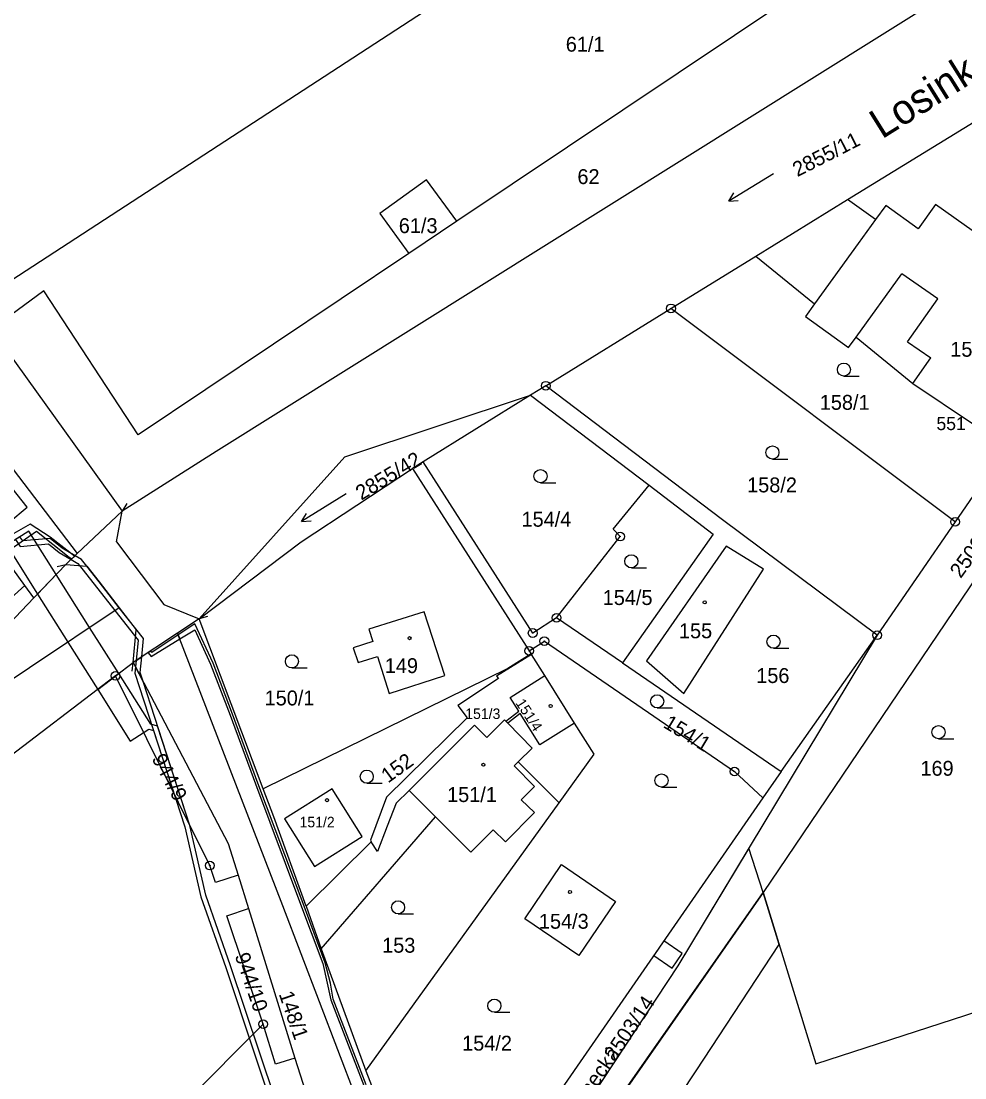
# Model space of a CAD drawing. Extents: x -562167 to -556918, y -1077891 to -1070763.
# Drawn here: x -558406.7 to -558298.9, y -1073028.6 to -1072907.9 of the extents above; entities that cross this region are included whole.
import ezdxf

# ---------------------------------------------------------------- set-up
doc = ezdxf.new("R2010")
doc.units = 0
for name, color, linetype in [('Hranice parcel', 7, 'Continuous'), ('Parcelní čísla', 7, 'Continuous'), ('Pop  PČ popisy', 7, 'Continuous'), ('Vnitřní kresba', 7, 'Continuous'), ('Věcná břemena k části', 7, 'Continuous'), ('Značky bodu BP', 7, 'Continuous'), ('Značky budov', 7, 'Continuous'), ('Značky kultur', 7, 'Continuous')]:
    doc.layers.add(name, color=color, linetype=linetype)

msp = doc.modelspace()

# ---------------------------------------------------------------- linework, layer by layer
at = {"layer": 'Hranice parcel'}
for p, q in [((-558412.27, -1072940.34), (-558302.75, -1072869.11)), ((-558360.38, -1072926.01), (-558365.72, -1072929.88)), ((-558356.9, -1072930.74), (-558360.38, -1072926.01)), ((-558322.75, -1072934.72), (-558312.27, -1072928.27)), ((-558309.07, -1072930.54), (-558312.27, -1072928.27)), ((-558365.72, -1072929.88), (-558362.39, -1072934.42)), ((-558307.91, -1072928.94), (-558309.07, -1072930.54)), ((-558356.9, -1072930.74), (-558362.39, -1072934.42)), ((-558332.45, -1072940.7), (-558322.75, -1072934.72)), ((-558322.75, -1072934.72), (-558316.04, -1072940.16)), ((-558346.76, -1072949.53), (-558332.45, -1072940.7)), ((-558299.99, -1072965.07), (-558332.45, -1072940.7)), ((-558410.09, -1072943.08), (-558395.16, -1072963.84)), ((-558346.76, -1072949.53), (-558348.49, -1072950.6)), ((-558348.49, -1072950.6), (-558360.75, -1072958.22)), ((-558348.49, -1072950.6), (-558334.96, -1072960.89)), ((-558360.75, -1072958.22), (-558361.97, -1072958.98)), ((-558348.25, -1072977.77), (-558360.75, -1072958.22)), ((-558361.97, -1072958.98), (-558348.65, -1072979.81)), ((-558339.04, -1072965.93), (-558334.96, -1072960.89)), ((-558400.29, -1072968.7), (-558395.16, -1072963.84)), ((-558299.99, -1072965.07), (-558308.9, -1072978.03)), ((-558400.29, -1072968.7), (-558401.61, -1072969.95)), ((-558401.61, -1072969.95), (-558405.23, -1072973.76)), ((-558462.61, -1073022.54), (-558406.26, -1072972.36)), ((-558405.23, -1072973.76), (-558406.26, -1072972.36)), ((-558386.36, -1072976.14), (-558388.83, -1072977.78)), ((-558379.04, -1072995.57), (-558386.36, -1072976.14)), ((-558345.52, -1072976.03), (-558348.25, -1072977.77)), ((-558338, -1072981.18), (-558345.52, -1072976.03)), ((-558388.83, -1072977.78), (-558393.89, -1072981.14)), ((-558319.87, -1072993.6), (-558308.9, -1072978.03)), ((-558348.65, -1072979.81), (-558346.92, -1072978.7)), ((-558346.92, -1072978.7), (-558325.2, -1072993.59)), ((-558348.65, -1072979.81), (-558348.44, -1072980.14)), ((-558348.39, -1072980.22), (-558348.44, -1072980.14)), ((-558346.87, -1072982.64), (-558348.39, -1072980.22)), ((-558395.91, -1072982.67), (-558393.89, -1072981.14)), ((-558338, -1072981.18), (-558319.87, -1072993.6)), ((-558395.91, -1072982.67), (-558409.32, -1072992.86)), ((-558385.14, -1073004.33), (-558395.91, -1072982.67)), ((-558343.46, -1072988.05), (-558346.87, -1072982.64)), ((-558349.9, -1072992.48), (-558345.24, -1072997.18)), ((-558325.2, -1072993.59), (-558321.94, -1072996.58)), ((-558319.87, -1072993.6), (-558321.94, -1072996.58)), ((-558367.31, -1073027.78), (-558345.24, -1072997.18)), ((-558321.94, -1072996.58), (-558350.74, -1073038.18)), ((-558372.4, -1073013.83), (-558359.35, -1072998.75)), ((-558366.69, -1073001.61), (-558374.15, -1073008.96)), ((-558384.49, -1073006.28), (-558385.14, -1073004.33)), ((-558381.92, -1073005.41), (-558384.49, -1073006.28)), ((-558381.92, -1073005.41), (-558380.73, -1073009.23)), ((-558383.21, -1073010.07), (-558380.73, -1073009.23)), ((-558380.73, -1073009.23), (-558375.41, -1073026.31)), ((-558374.15, -1073008.96), (-558372.4, -1073013.83)), ((-558379.05, -1073022.44), (-558383.21, -1073010.07)), ((-558372.4, -1073013.83), (-558367.31, -1073027.78)), ((-558397.33, -1073040.74), (-558379.05, -1073022.44)), ((-558377.65, -1073026.99), (-558379.05, -1073022.44)), ((-558375.41, -1073026.31), (-558377.65, -1073026.99)), ((-558375.41, -1073026.31), (-558374.22, -1073030.13))]:
    msp.add_line(p, q, dxfattribs=at)
for points in [[(-558502.85, -1072847.47), (-558483.15, -1072864.47), (-558456.76, -1072894.62), (-558400.29, -1072968.7)], [(-558294.24, -1072880.85), (-558298.44, -1072890.96), (-558299.92, -1072892.58), (-558356.9, -1072930.74)], [(-558289.19, -1072887.81), (-558290.8, -1072891.97), (-558300.9, -1072904.77), (-558384.43, -1072957.06), (-558395.16, -1072963.84)], [(-558312.27, -1072928.27), (-558297.82, -1072919.38), (-558297.58, -1072919.21)], [(-558286.49, -1072939.41), (-558295.68, -1072933.46), (-558302.22, -1072928.82), (-558304.22, -1072931.62), (-558307.91, -1072928.94)], [(-558362.39, -1072934.42), (-558393.32, -1072955.13), (-558404.11, -1072938.68), (-558410.09, -1072943.08)], [(-558316.04, -1072940.16), (-558317.1, -1072941.63), (-558312.15, -1072945.18), (-558311.29, -1072944)], [(-558311.29, -1072944), (-558304.8, -1072949.26), (-558298.02, -1072953.85), (-558292.55, -1072945.86), (-558293.35, -1072945.29), (-558292.99, -1072944.69), (-558291.91, -1072944.56), (-558290.96, -1072943.22), (-558291.26, -1072942.13), (-558290.89, -1072941.55), (-558287.69, -1072942.86)], [(-558287.69, -1072942.86), (-558288.1, -1072946.44), (-558295.88, -1072959.09), (-558299.99, -1072965.07)], [(-558308.9, -1072978.03), (-558326.55, -1072964.86), (-558346.76, -1072949.53)], [(-558386.36, -1072976.14), (-558369.71, -1072957.67), (-558348.49, -1072950.6)], [(-558406.26, -1072972.36), (-558410.25, -1072966.91), (-558406.02, -1072963.38), (-558412.6, -1072955.11)], [(-558386.36, -1072976.14), (-558374.72, -1072967.37), (-558361.97, -1072958.98)], [(-558334.96, -1072960.89), (-558327.62, -1072966.48), (-558338, -1072981.18)], [(-558289.9, -1072961.05), (-558292.03, -1072963.19), (-558321.91, -1073007.39)], [(-558345.52, -1072976.03), (-558338.27, -1072966.76), (-558339.04, -1072965.93)], [(-558326.16, -1072967.85), (-558335.25, -1072980.94), (-558331, -1072984.68), (-558321.87, -1072970.49), (-558326.16, -1072967.85)], [(-558401.61, -1072969.95), (-558399.19, -1072970.13), (-558397.79, -1072971.93), (-558395.5, -1072974.88)], [(-558405.23, -1072973.76), (-558412.32, -1072981.19), (-558462.01, -1073023.32)], [(-558395.5, -1072974.88), (-558416.04, -1072988.58), (-558459.2, -1073023.8), (-558471.43, -1073037.29), (-558467.94, -1073057.14)], [(-558358.29, -1072982.64), (-558360.65, -1072975.35), (-558366.97, -1072977.34), (-558366.52, -1072978.75), (-558368.77, -1072979.46), (-558368.18, -1072981.15), (-558365.98, -1072980.45), (-558364.65, -1072984.66), (-558358.29, -1072982.64)], [(-558360.05, -1073052.77), (-558376.81, -1073008.93), (-558388.83, -1072977.78)], [(-558308.9, -1072978.03), (-558331.65, -1073015.79), (-558358.56, -1073056.51), (-558360.05, -1073052.77)], [(-558348.44, -1072980.14), (-558351.11, -1072981.83), (-558379.04, -1072995.57)], [(-558348.39, -1072980.22), (-558352.37, -1072982.69), (-558352.17, -1072982.97), (-558356.82, -1072986.06), (-558355.74, -1072987.46), (-558364.94, -1072996.53), (-558366.8, -1073001.43), (-558366.69, -1073001.61)], [(-558393.89, -1072981.14), (-558383.05, -1073001.79), (-558381.92, -1073005.41)], [(-558351.33, -1072987.85), (-558349.83, -1072986.71), (-558350.82, -1072985.12), (-558346.87, -1072982.64)], [(-558351.33, -1072987.85), (-558351.48, -1072987.69), (-558353.49, -1072989.7), (-558354.91, -1072988.29), (-558362.36, -1072995.74), (-558363.86, -1072997.19), (-558364.86, -1072999.81), (-558365.97, -1073002.72), (-558366.69, -1073001.61)], [(-558343.46, -1072988.05), (-558347.43, -1072990.54), (-558349.67, -1072986.97), (-558351.11, -1072988.06), (-558351.33, -1072987.85)], [(-558345.24, -1072997.18), (-558341.23, -1072991.61), (-558343.46, -1072988.05)], [(-558359.35, -1072998.75), (-558355.3, -1073002.8), (-558352.75, -1073000.26), (-558351.35, -1073001.6), (-558348.05, -1072998.26), (-558349.57, -1072996.82), (-558348.03, -1072995.3), (-558350.35, -1072992.93), (-558349.9, -1072992.48)], [(-558374.15, -1073008.96), (-558377.82, -1072998.76), (-558379.04, -1072995.57)], [(-558373.18, -1073004.43), (-558367.72, -1073001), (-558371.16, -1072995.55), (-558376.62, -1072998.98), (-558373.18, -1073004.43)], [(-558342.98, -1073014.61), (-558349.16, -1073010.4), (-558344.95, -1073004.22), (-558338.78, -1073008.45), (-558342.98, -1073014.61)], [(-558321.91, -1073007.39), (-558348.49, -1073045.41), (-558357.24, -1073057.99)], [(-558321.91, -1073007.39), (-558315.9, -1073026.96), (-558290.19, -1073018.62)], [(-558367.31, -1073027.78), (-558362.99, -1073039.01), (-558356.93, -1073040.23), (-558352.91, -1073040.63), (-558350.74, -1073038.18)]]:
    msp.add_lwpolyline(points, dxfattribs=at)
at = {"layer": 'Vnitřní kresba'}
for p, q in [((-558309.07, -1072930.54), (-558311.07, -1072933.3)), ((-558311.07, -1072933.3), (-558316.04, -1072940.16)), ((-558311.29, -1072944), (-558306.06, -1072936.77)), ((-558301.97, -1072939.61), (-558306.06, -1072936.77)), ((-558305.42, -1072944.53), (-558301.97, -1072939.61)), ((-558305.42, -1072944.53), (-558302.77, -1072946.35)), ((-558304.8, -1072949.26), (-558302.77, -1072946.35)), ((-558394.64, -1072962.98), (-558395.16, -1072963.84)), ((-558395.82, -1072967.36), (-558395.16, -1072963.84)), ((-558395.82, -1072967.36), (-558394.29, -1072969.38)), ((-558394.29, -1072969.38), (-558390.4, -1072974.53)), ((-558402.58, -1072970.19), (-558401.61, -1072969.95)), ((-558390.4, -1072974.53), (-558386.36, -1072976.14)), ((-558395.5, -1072974.88), (-558393.54, -1072977.41)), ((-558385.39, -1072975.88), (-558386.36, -1072976.14)), ((-558393.89, -1072981.14), (-558393.54, -1072977.41)), ((-558394.03, -1072982.13), (-558393.89, -1072981.14)), ((-558351.11, -1072988.06), (-558348.3, -1072990.92)), ((-558349.9, -1072992.48), (-558348.3, -1072990.92)), ((-558362.36, -1072995.74), (-558361.55, -1072996.55)), ((-558361.55, -1072996.55), (-558359.35, -1072998.75))]:
    msp.add_line(p, q, dxfattribs=at)
at = {"layer": 'Věcná břemena k části'}
for points in [[(-558404.96, -1072966.15), (-558401.2, -1072969.12), (-558400.92, -1072969.3), (-558400.62, -1072969.01), (-558403.38, -1072966.82), (-558405.66, -1072965.34), (-558409.71, -1072967.64), (-558408.83, -1072968.85)], [(-558408.35, -1072967.75), (-558404.82, -1072973.33), (-558402.69, -1072971.09), (-558405.81, -1072966.15)], [(-558407.33, -1072967.11), (-558406.82, -1072967.9), (-558403.57, -1072967.6), (-558402.34, -1072968.59), (-558401, -1072969.37), (-558400.54, -1072968.94), (-558402, -1072968.09), (-558403.39, -1072966.98), (-558406.52, -1072967.26), (-558406.83, -1072966.79)], [(-558395.98, -1072975.2), (-558393.32, -1072978.58), (-558393.55, -1072980.92), (-558392.91, -1072980.49), (-558392.7, -1072978.4), (-558395.5, -1072974.88), (-558397.79, -1072971.93), (-558399.19, -1072970.13), (-558399.81, -1072969.37), (-558400.54, -1072968.94), (-558401, -1072969.37), (-558400.21, -1072969.83), (-558400.02, -1072970.07)], [(-558401.37, -1072978.8), (-558397.95, -1072984.22), (-558395.55, -1072982.4), (-558398.87, -1072977.13), (-558402.69, -1072971.09), (-558404.82, -1072973.33)], [(-558391.75, -1072980), (-558391.89, -1072979.81), (-558392.2, -1072980.02), (-558391.86, -1072980.45), (-558388.58, -1072978.44), (-558388.75, -1072977.99)], [(-558393.55, -1072980.92), (-558393.63, -1072981.64), (-558392.75, -1072983.32), (-558393.09, -1072982.28), (-558392.91, -1072980.49)], [(-558367.49, -1073062.05), (-558367.33, -1073060.92), (-558371.08, -1073052.48), (-558376.05, -1073035.85), (-558382.76, -1073015.77), (-558385.59, -1073007.72), (-558387.41, -1072999.74), (-558392.75, -1072983.32), (-558393.63, -1072981.64), (-558393.69, -1072982.34), (-558387.99, -1072999.9), (-558386.17, -1073007.88), (-558383.32, -1073015.97), (-558376.71, -1073035.79), (-558377.06, -1073035.98), (-558376.78, -1073036.51), (-558376.52, -1073036.37), (-558371.64, -1073052.68)], [(-558392.09, -1072988.76), (-558391.56, -1072988.89), (-558387.99, -1072999.9), (-558386.17, -1073007.88), (-558383.32, -1073015.97), (-558376.71, -1073035.79), (-558376.52, -1073036.37), (-558371.64, -1073052.68), (-558367.49, -1073062.05), (-558367.33, -1073060.92), (-558371.08, -1073052.48), (-558376.05, -1073035.85), (-558382.76, -1073015.77), (-558385.59, -1073007.72), (-558387.41, -1072999.74), (-558391.1, -1072988.39), (-558391.89, -1072988.19), (-558395.55, -1072982.4), (-558397.95, -1072984.22), (-558394.23, -1072990.11)], [(-558321.91, -1073007.39), (-558323.54, -1073002.33), (-558331.65, -1073015.79), (-558358.56, -1073056.51), (-558359.57, -1073058.1), (-558362.56, -1073062.72), (-558371.61, -1073078.42), (-558369.34, -1073079.8), (-558362.54, -1073067.55), (-558360.35, -1073074.19), (-558354.71, -1073065.77), (-558357.24, -1073057.99), (-558348.49, -1073045.41)], [(-558321.91, -1073007.39), (-558357.24, -1073057.99), (-558347.91, -1073055.5), (-558340.56, -1073044.32), (-558329.58, -1073027.78), (-558320.08, -1073013.34)], [(-558332.31, -1073016.05), (-558331.16, -1073014.38), (-558333.25, -1073012.93), (-558334.41, -1073014.6)]]:
    msp.add_lwpolyline(points, close=True, dxfattribs=at)
msp.add_lwpolyline([(-558367.28, -1073029.35), (-558371.03, -1073019.59), (-558371.36, -1073017.74), (-558371.95, -1073015.42), (-558374.6, -1073008.34), (-558379.65, -1072994.91), (-558382.54, -1072987.05), (-558384.77, -1072981.22), (-558386.85, -1072976.71), (-558388.75, -1072977.99), (-558388.58, -1072978.44), (-558386.87, -1072977.39), (-558385.05, -1072981.33), (-558382.81, -1072987.15), (-558379.93, -1072995.01), (-558374.88, -1073008.44), (-558372.23, -1073015.51), (-558371.32, -1073019.67), (-558367.56, -1073029.45)], dxfattribs=at)
at = {"layer": 'Značky bodu BP'}
for centre, radius in [((-558332.45, -1072940.7), 0.5), ((-558332.45, -1072940.7), 0.0303), ((-558346.76, -1072949.53), 0.5), ((-558346.76, -1072949.53), 0.0303), ((-558299.99, -1072965.07), 0.5), ((-558299.99, -1072965.07), 0.0303), ((-558338.27, -1072966.76), 0.5), ((-558338.27, -1072966.76), 0.0303), ((-558345.52, -1072976.03), 0.5), ((-558345.52, -1072976.03), 0.0303), ((-558348.25, -1072977.77), 0.5), ((-558348.25, -1072977.77), 0.0303), ((-558346.92, -1072978.7), 0.5), ((-558308.9, -1072978.03), 0.5), ((-558308.9, -1072978.03), 0.0303), ((-558348.65, -1072979.81), 0.5), ((-558346.92, -1072978.7), 0.0303), ((-558348.65, -1072979.81), 0.0303), ((-558395.91, -1072982.67), 0.5), ((-558395.91, -1072982.67), 0.0303), ((-558325.2, -1072993.59), 0.5), ((-558325.2, -1072993.59), 0.0303), ((-558385.14, -1073004.33), 0.5), ((-558385.14, -1073004.33), 0.0303), ((-558379.05, -1073022.44), 0.5), ((-558379.05, -1073022.44), 0.0303)]:
    msp.add_circle(centre, radius, dxfattribs=at)
at = {"layer": 'Značky budov'}
for centre in [(-558328.6, -1072974.27), (-558362.32, -1072978.36), (-558346.2, -1072986.1), (-558353.89, -1072992.82), (-558371.76, -1072996.86), (-558343.99, -1073007.35)]:
    msp.add_circle(centre, 0.175, dxfattribs=at)
at = {"layer": 'Značky kultur'}
for p, q in [((-558320.72, -1072925.35), (-558325.86, -1072928.44)), ((-558325.86, -1072928.44), (-558325.28, -1072927.5)), ((-558325.86, -1072928.44), (-558324.77, -1072928.36)), ((-558312.69, -1072948.44), (-558310.94, -1072948.44)), ((-558320.86, -1072957.91), (-558319.11, -1072957.91)), ((-558347.36, -1072960.61), (-558345.61, -1072960.61)), ((-558369.57, -1072961.87), (-558374.66, -1072965.05)), ((-558374.66, -1072965.05), (-558374.1, -1072964.11)), ((-558374.66, -1072965.05), (-558373.57, -1072964.96)), ((-558336.98, -1072970.33), (-558335.23, -1072970.33)), ((-558320.74, -1072979.51), (-558318.99, -1072979.51)), ((-558375.76, -1072981.76), (-558374.01, -1072981.76)), ((-558334.03, -1072986.32), (-558332.28, -1072986.32)), ((-558301.88, -1072989.85), (-558300.13, -1072989.85)), ((-558367.21, -1072994.92), (-558365.46, -1072994.92)), ((-558333.54, -1072995.36), (-558331.79, -1072995.36)), ((-558363.63, -1073009.85), (-558361.88, -1073009.85)), ((-558352.63, -1073021.08), (-558350.88, -1073021.08))]:
    msp.add_line(p, q, dxfattribs=at)
for centre in [(-558312.69, -1072947.69), (-558320.86, -1072957.16), (-558347.36, -1072959.86), (-558336.98, -1072969.58), (-558320.74, -1072978.76), (-558375.76, -1072981.01), (-558334.03, -1072985.57), (-558301.88, -1072989.1), (-558367.21, -1072994.17), (-558333.54, -1072994.61), (-558363.63, -1073009.1), (-558352.63, -1073020.33)]:
    msp.add_circle(centre, 0.75, dxfattribs=at)

# ---------------------------------------------------------------- texts
at = {"layer": 'Parcelní čísla'}
for s, height, p in [('61/1', 1.7, (-558344.47, -1072911.38)), ('62', 1.7, (-558343.14, -1072926.5)), ('61/3', 1.7, (-558363.55, -1072932.1)), ('157', 1.7, (-558300.54, -1072946.22)), ('158/1', 1.7, (-558315.45, -1072952.28)), ('158/2', 1.7, (-558323.75, -1072961.71)), ('154/4', 1.7, (-558349.53, -1072965.63)), ('154/5', 1.7, (-558340.25, -1072974.57)), ('155', 1.7, (-558331.54, -1072978.37)), ('149', 1.7, (-558365.15, -1072982.35)), ('156', 1.7, (-558322.71, -1072983.48)), ('150/1', 1.7, (-558378.88, -1072986.04)), ('151/3', 1.2, (-558355.96, -1072987.59)), ('169', 1.7, (-558303.95, -1072994.07)), ('151/1', 1.7, (-558358.03, -1072997.07)), ('151/2', 1.2, (-558374.89, -1072999.96)), ('154/3', 1.7, (-558347.54, -1073011.54)), ('153', 1.7, (-558365.45, -1073014.28)), ('154/2', 1.7, (-558356.31, -1073025.46))]:
    msp.add_text(s, height=height, dxfattribs=at).set_placement(p)
for s, height, rotation, p in [('2855/11', 1.7, 27, (-558318.01, -1072925.72)), ('2855/42', 1.7, 31, (-558367.83, -1072962.66)), ('2503/4', 1.7, 54, (-558299.35, -1072971.61)), ('151/4', 1.2, 303, (-558350.26, -1072985.76)), ('154/1', 1.7, 329, (-558333.45, -1072988.48)), ('944/9', 1.7, 298, (-558391.82, -1072992.11)), ('152', 1.7, 36, (-558364.78, -1072994.97)), ('944/10', 1.7, 289, (-558382.31, -1073014.61)), ('148/1', 1.7, 289, (-558377.28, -1073018.99)), ('2503/14', 1.7, 56, (-558338.82, -1073026.76))]:
    msp.add_text(s, height=height, rotation=rotation, dxfattribs=at).set_placement(p)
at = {"layer": 'Pop  PČ popisy'}
for s, height, rotation, p in [('Losinka', 3.4, 32, (-558308.35, -1072921.42)), ('Zámecká', 1.7, 55, (-558343.52, -1073033.45))]:
    msp.add_text(s, height=height, rotation=rotation, dxfattribs=at).set_placement(p)
at = {"layer": 'Značky bodu BP'}
msp.add_text('551', height=1.5, dxfattribs=at).set_placement((-558302.12, -1072954.6))

doc.saveas('drawing.dxf')
